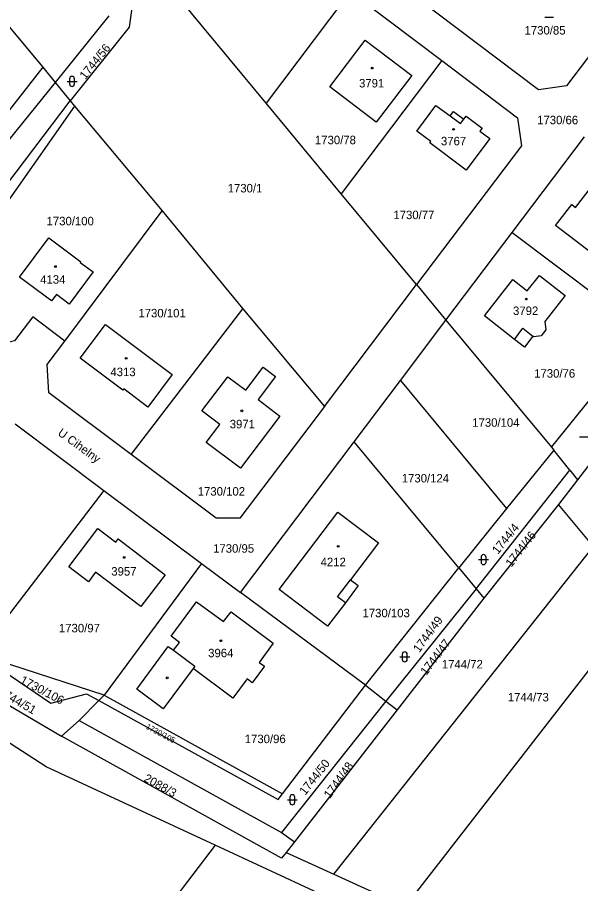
# Model space of a CAD drawing. Extents: x -679220 to -673243, y -1075091 to -1066557.
# Drawn here: x -677126.9 to -677014, y -1072559.9 to -1072386.3 of the extents above; entities that cross this region are included whole.
import ezdxf

# ---------------------------------------------------------------- set-up
doc = ezdxf.new("R2010")
doc.units = 0
for name, color, linetype in [('Hranice parcel', 7, 'Continuous'), ('Parcelní čísla', 7, 'Continuous'), ('Pop  PČ popisy', 7, 'Continuous'), ('Vnitřní kresba', 7, 'Continuous'), ('Značky budov', 7, 'Continuous'), ('Značky kultur', 7, 'Continuous')]:
    doc.layers.add(name, color=color, linetype=linetype)

msp = doc.modelspace()

# ---------------------------------------------------------------- linework, layer by layer
at = {"layer": 'Hranice parcel'}
for p, q in [((-677077.02, -1072403.48), (-677099.4, -1072376.48)), ((-677133.56, -1072382.2), (-677121.78, -1072396.3)), ((-677060.11, -1072381.11), (-677077.02, -1072403.48)), ((-677060.11, -1072381.11), (-677041.76, -1072394.98)), ((-677108.5, -1072386.03), (-677119.32, -1072399.39)), ((-677041.76, -1072394.98), (-677061.93, -1072421.67)), ((-677121.78, -1072396.3), (-677137.23, -1072416.05)), ((-677121.78, -1072396.3), (-677119.32, -1072399.39)), ((-677119.32, -1072399.39), (-677116.27, -1072403.07)), ((-677146.18, -1072442.44), (-677116.27, -1072403.07)), ((-677116.27, -1072403.07), (-677115.41, -1072404.11)), ((-677115.41, -1072404.11), (-677143.8, -1072444.26)), ((-677115.41, -1072404.11), (-677097.84, -1072425.09)), ((-677061.93, -1072421.67), (-677077.02, -1072403.48)), ((-677027.68, -1072429.42), (-677013.21, -1072410.27)), ((-677046.85, -1072439.86), (-677061.93, -1072421.67)), ((-677117.32, -1072451.18), (-677097.84, -1072425.09)), ((-677097.84, -1072425.09), (-677081.68, -1072444.73)), ((-677040.95, -1072446.98), (-677027.68, -1072429.42)), ((-677027.68, -1072429.42), (-677001.2, -1072449.42)), ((-677065.29, -1072464.28), (-677046.85, -1072439.86)), ((-677046.85, -1072439.86), (-677040.95, -1072446.98)), ((-677104.04, -1072473.94), (-677081.68, -1072444.73)), ((-677081.68, -1072444.73), (-677065.29, -1072464.28)), ((-677050.09, -1072459.1), (-677040.95, -1072446.98)), ((-677040.95, -1072446.98), (-677019.83, -1072472.45)), ((-677019.83, -1072472.45), (-677001.2, -1072449.42)), ((-677059.38, -1072471.41), (-677050.09, -1072459.1)), ((-677050.09, -1072459.1), (-677028.8, -1072484.76)), ((-677001.89, -1072462.45), (-677014.57, -1072478.97)), ((-677127.33, -1072467.78), (-677109.56, -1072481.11)), ((-677082.17, -1072501.58), (-677059.38, -1072471.41)), ((-677038.4, -1072496.66), (-677059.38, -1072471.41)), ((-677019.83, -1072472.45), (-677019.36, -1072473.04)), ((-677019.36, -1072473.04), (-677028.8, -1072484.76)), ((-677016.1, -1072477.07), (-677019.36, -1072473.04)), ((-677034.89, -1072500.86), (-677016.1, -1072477.07)), ((-677016.1, -1072477.07), (-677014.57, -1072478.97)), ((-677014.57, -1072478.97), (-677018.39, -1072483.95)), ((-677109.56, -1072481.11), (-677134.69, -1072513.93)), ((-677109.56, -1072481.11), (-677089.97, -1072495.79)), ((-677018.39, -1072483.95), (-677033.34, -1072502.73)), ((-677011.4, -1072492.35), (-677018.39, -1072483.95)), ((-677028.8, -1072484.76), (-677038.4, -1072496.66)), ((-677063.46, -1072557.99), (-677011.4, -1072492.35)), ((-677089.97, -1072495.79), (-677109.45, -1072522.17)), ((-677089.97, -1072495.79), (-677082.17, -1072501.58)), ((-677057.11, -1072520.12), (-677038.4, -1072496.66)), ((-677038.4, -1072496.66), (-677034.89, -1072500.86)), ((-677057.11, -1072520.12), (-677082.17, -1072501.58)), ((-677034.89, -1072500.86), (-677052.98, -1072523.33)), ((-677034.89, -1072500.86), (-677033.34, -1072502.73)), ((-677033.34, -1072502.73), (-677050.71, -1072525.09)), ((-677001.95, -1072503.72), (-677049.16, -1072564.49)), ((-677109.45, -1072522.17), (-677134.69, -1072513.93)), ((-677138.16, -1072518.56), (-677118.01, -1072530.39)), ((-677073.69, -1072541.89), (-677057.11, -1072520.12)), ((-677057.11, -1072520.12), (-677052.98, -1072523.33)), ((-677110.51, -1072523.23), (-677109.45, -1072522.17)), ((-677109.45, -1072522.17), (-677073.69, -1072541.89)), ((-677114.5, -1072527.2), (-677110.51, -1072523.23)), ((-677052.98, -1072523.33), (-677073.89, -1072549.68)), ((-677052.98, -1072523.33), (-677050.71, -1072525.09)), ((-677050.71, -1072525.09), (-677071.32, -1072551.51)), ((-677118.01, -1072530.39), (-677114.5, -1072527.2)), ((-677114.5, -1072527.2), (-677073.89, -1072549.68)), ((-677073.89, -1072549.68), (-677071.32, -1072551.51)), ((-677087.25, -1072552.22), (-677169.3, -1072659.82)), ((-677066.53, -1072561.86), (-677087.25, -1072552.22)), ((-677071.32, -1072551.51), (-677073, -1072553.66)), ((-677073, -1072553.66), (-677063.46, -1072557.99)), ((-677063.46, -1072557.99), (-677049.16, -1072564.49))]:
    msp.add_line(p, q, dxfattribs=at)
for points in [[(-677002.92, -1072381.7), (-677016.78, -1072400.05), (-677022.38, -1072400.83), (-677047.12, -1072382.15), (-677047.9, -1072376.55), (-677034.04, -1072358.2)], [(-677103.27, -1072379.56), (-677104.47, -1072388.26), (-677116.27, -1072403.07)], [(-677047.81, -1072397.98), (-677054.93, -1072407.31), (-677064.23, -1072400.21), (-677057.13, -1072390.86), (-677047.81, -1072397.98)], [(-677041.76, -1072394.98), (-677026.61, -1072406.42), (-677025.82, -1072412.03), (-677046.85, -1072439.86)], [(-677119.32, -1072399.39), (-677141.89, -1072427.23), (-677151.03, -1072438.75)], [(-677039.44, -1072405.16), (-677037.37, -1072406.7), (-677036.92, -1072406.1), (-677033.71, -1072408.49), (-677034.15, -1072409.1), (-677032.15, -1072410.59), (-677036.89, -1072416.94), (-677044.17, -1072411.46), (-677044.01, -1072411.22), (-677046.8, -1072409.1), (-677042.96, -1072403.99), (-677040.13, -1072406.04), (-677039.44, -1072405.16)], [(-677018.97, -1072428.02), (-677015.75, -1072423.84), (-677014.96, -1072424.44), (-677011.75, -1072420.27), (-677010.89, -1072420.93), (-677008.7, -1072418.05), (-677003.29, -1072422.23), (-677005.47, -1072425.12), (-677004.97, -1072425.5), (-677011.41, -1072433.85), (-677018.97, -1072428.02)], [(-677119.05, -1072441.88), (-677120, -1072443.15), (-677126.42, -1072438.36), (-677120.57, -1072430.5), (-677114.15, -1072435.29), (-677114.25, -1072435.43), (-677111.69, -1072437.34), (-677116.51, -1072443.78), (-677119.05, -1072441.88)], [(-677021.12, -1072447.24), (-677020.95, -1072448.94), (-677021.86, -1072450.15), (-677023.36, -1072450.34), (-677023.54, -1072450.2), (-677025.24, -1072452.42), (-677027.25, -1072450.84), (-677033.24, -1072446.14), (-677027.58, -1072438.82), (-677024.66, -1072441.15), (-677022.18, -1072438.05), (-677017.08, -1072442.05), (-677021.12, -1072447.24)], [(-677117.32, -1072451.18), (-677123.77, -1072446.31), (-677127.42, -1072451.16), (-677132.84, -1072452.48), (-677139.28, -1072447.65), (-677143.8, -1072444.26)], [(-677105.55, -1072460.76), (-677105.72, -1072461.01), (-677114.26, -1072454.6), (-677109.23, -1072447.9), (-677095.86, -1072457.92), (-677100.72, -1072464.41), (-677105.55, -1072460.76)], [(-677104.04, -1072473.94), (-677120.59, -1072461.57), (-677120.9, -1072455.86), (-677117.32, -1072451.18)], [(-677086.27, -1072467.91), (-677089.86, -1072465.19), (-677084.67, -1072458.33), (-677081.09, -1072461.05), (-677077.58, -1072456.43), (-677075.12, -1072458.29), (-677078.61, -1072462.92), (-677074.23, -1072466.24), (-677082.13, -1072476.68), (-677088.99, -1072471.49), (-677086.27, -1072467.91)], [(-677065.29, -1072464.28), (-677082.26, -1072486.71), (-677087.03, -1072486.71), (-677104.04, -1072473.94)], [(-677062.64, -1072485.45), (-677054.48, -1072491.63), (-677060.1, -1072499.03), (-677058.54, -1072500.17), (-677061.1, -1072503.67), (-677064.69, -1072508.35), (-677074.4, -1072500.98), (-677062.64, -1072485.45)], [(-677087.25, -1072552.22), (-677121.06, -1072536.49), (-677175.82, -1072501.1), (-677185.37, -1072494.11), (-677191.65, -1072489.1)], [(-677107.13, -1072491.5), (-677106.66, -1072490.84), (-677097.22, -1072498.02), (-677102.1, -1072504.41), (-677111.19, -1072497.48), (-677112.61, -1072499.42), (-677116.58, -1072496.4), (-677110.77, -1072488.72), (-677107.13, -1072491.5)], [(-677080.81, -1072518.9), (-677083.65, -1072522.72), (-677091.65, -1072516.8), (-677097.62, -1072524.86), (-677102.94, -1072520.94), (-677096.64, -1072512.39), (-677095.6, -1072513.13), (-677094.39, -1072511.62), (-677096.07, -1072510.34), (-677090.95, -1072503.42), (-677085.53, -1072507.41), (-677084.01, -1072505.46), (-677075.56, -1072511.73), (-677078.37, -1072515.61), (-677077.34, -1072516.35), (-677079.78, -1072519.7), (-677080.81, -1072518.9)], [(-677134.69, -1072513.93), (-677120.16, -1072523.75), (-677112.98, -1072521.87), (-677110.51, -1072523.23)], [(-677110.51, -1072523.23), (-677074.6, -1072543.08), (-677073.69, -1072541.89)], [(-677073, -1072553.66), (-677073.93, -1072554.84), (-677118.01, -1072530.39)]]:
    msp.add_lwpolyline(points, dxfattribs=at)
at = {"layer": 'Vnitřní kresba'}
for p, q in [((-677040.13, -1072406.04), (-677038.05, -1072407.59)), ((-677038.05, -1072407.59), (-677037.37, -1072406.7)), ((-677027.25, -1072450.84), (-677025.52, -1072448.61)), ((-677025.52, -1072448.61), (-677023.54, -1072450.2)), ((-677062.7, -1072502.45), (-677060.1, -1072499.03)), ((-677061.1, -1072503.67), (-677062.7, -1072502.45)), ((-677095.6, -1072513.13), (-677091.29, -1072516.32)), ((-677091.29, -1072516.32), (-677091.65, -1072516.8))]:
    msp.add_line(p, q, dxfattribs=at)
at = {"layer": 'Značky budov'}
for centre in [(-677055.73, -1072396.48), (-677039.43, -1072408.75), (-677119.24, -1072436.26), (-677024.84, -1072442.77), (-677105.05, -1072454.64), (-677081.87, -1072465.17), (-677062.55, -1072492.32), (-677105.44, -1072494.54), (-677086.08, -1072511.24), (-677096.82, -1072518.67)]:
    msp.add_circle(centre, 0.175, dxfattribs=at)
at = {"layer": 'Značky kultur'}
for p, q in [((-677021.12, -1072386.31), (-677019.37, -1072386.31)), ((-677116.91, -1072399.16), (-677114.91, -1072399.16)), ((-677116.41, -1072398.66), (-677116.41, -1072399.66)), ((-677115.41, -1072399.66), (-677115.41, -1072398.66)), ((-677014.19, -1072470.41), (-677012.19, -1072470.41)), ((-677034.42, -1072494.99), (-677032.42, -1072494.99)), ((-677033.92, -1072494.49), (-677033.92, -1072495.49)), ((-677032.92, -1072495.49), (-677032.92, -1072494.49)), ((-677049.72, -1072513.97), (-677049.72, -1072514.97)), ((-677048.72, -1072514.97), (-677048.72, -1072513.97)), ((-677050.22, -1072514.47), (-677048.22, -1072514.47)), ((-677072.75, -1072543.11), (-677070.75, -1072543.11)), ((-677072.25, -1072542.61), (-677072.25, -1072543.61)), ((-677071.25, -1072543.61), (-677071.25, -1072542.61))]:
    msp.add_line(p, q, dxfattribs=at)
for centre, start, end in [((-677115.91, -1072398.66), 0, 180), ((-677115.91, -1072399.66), 180, 359.9879), ((-677033.42, -1072494.49), 0, 180), ((-677033.42, -1072495.49), 180, 359.9879), ((-677049.22, -1072513.97), 0, 180), ((-677049.22, -1072514.97), 180, 359.9879), ((-677071.75, -1072542.61), 0, 180), ((-677071.75, -1072543.61), 180, 359.9879)]:
    msp.add_arc(centre, 0.5, start, end, dxfattribs=at)

# ---------------------------------------------------------------- texts
at = {"layer": 'Parcelní čísla'}
for s, p in [('1730/85', (-677025.2, -1072389.76)), ('3791', (-677058.38, -1072400.36)), ('1730/66', (-677022.68, -1072407.74)), ('1730/78', (-677067.22, -1072411.74)), ('3767', (-677041.96, -1072411.96)), ('1730/1', (-677084.71, -1072421.4)), ('1730/77', (-677051.49, -1072426.75)), ('1730/100', (-677121.01, -1072427.99)), ('4134', (-677122.29, -1072439.69)), ('1730/101', (-677102.6, -1072446.44)), ('3792', (-677027.51, -1072445.96)), ('4313', (-677108.22, -1072458.22)), ('1730/76', (-677023.27, -1072458.52)), ('3971', (-677084.3, -1072468.67)), ('1730/104', (-677035.69, -1072468.36)), ('1730/124', (-677049.81, -1072479.52)), ('1730/102', (-677090.71, -1072482.16)), ('1730/95', (-677087.63, -1072493.6)), ('4212', (-677066.08, -1072496.3)), ('3957', (-677108.04, -1072498.19)), ('1730/103', (-677057.68, -1072506.54)), ('1730/97', (-677118.54, -1072509.56)), ('3964', (-677088.62, -1072514.55)), ('1744/72', (-677041.77, -1072516.79)), ('1744/73', (-677028.56, -1072523.4)), ('1730/96', (-677081.29, -1072531.76))]:
    msp.add_text(s, height=1.7, dxfattribs=at).set_placement(p)
for s, height, rotation, p in [('1744/56', 1.7, 51, (-677113.25, -1072398.89)), ('1744/4', 1.7, 51, (-677030.54, -1072494.02)), ('1744/46', 1.7, 52, (-677027.84, -1072496.61)), ('1744/49', 1.7, 54, (-677046.31, -1072513.75)), ('1744/47', 1.7, 53, (-677044.88, -1072518.29)), ('1730/106', 1.7, 332, (-677126.47, -1072519.63)), ('1744/51', 1.7, 330, (-677130.83, -1072521.94)), ('1730/105', 1.14, 332, (-677101.21, -1072528.82)), ('1744/50', 1.7, 52, (-677069.16, -1072542.32)), ('1744/48', 1.7, 54, (-677064.22, -1072542.97)), ('2088/3', 1.7, 331, (-677101.65, -1072539.31))]:
    msp.add_text(s, height=height, rotation=rotation, dxfattribs=at).set_placement(p)
at = {"layer": 'Pop  PČ popisy'}
msp.add_text('U Cihelny', height=1.7, rotation=324, dxfattribs=at).set_placement((-677118.92, -1072469.92))

doc.saveas('drawing.dxf')
